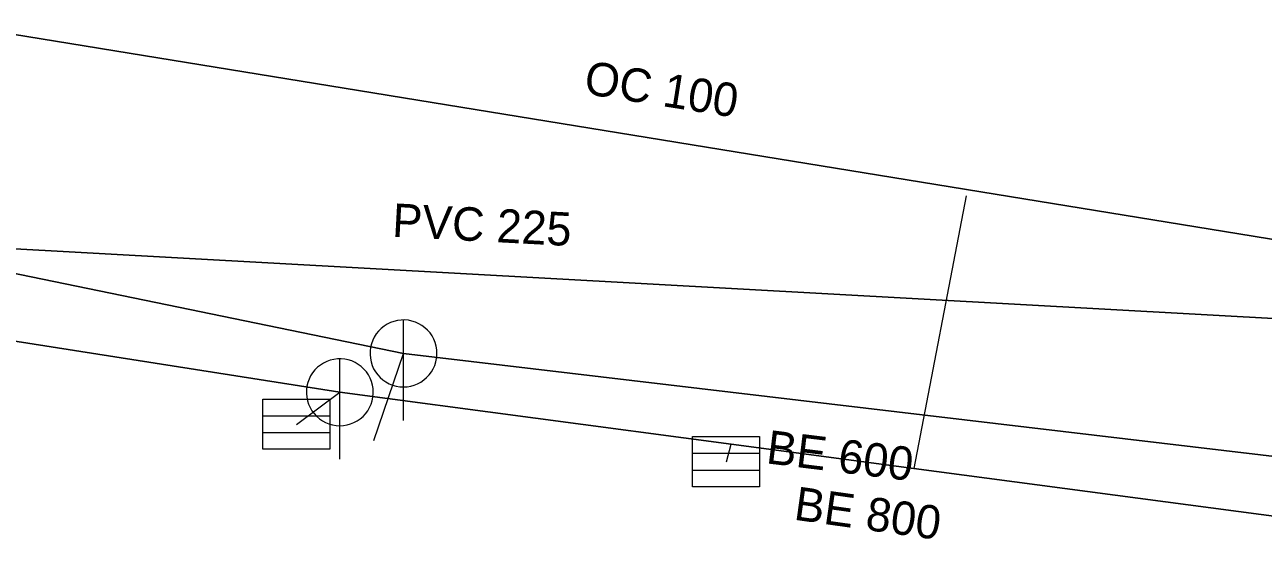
# Model space of a CAD drawing. Extents: x -659250 to -657316, y -997555 to -993684.
# Drawn here: x -658675.14 to -658638.15, y -994986.49 to -994971.06 of the extents above; entities that cross this region are included whole.
import ezdxf

# ---------------------------------------------------------------- set-up
doc = ezdxf.new("R2010")
doc.units = 0
doc.header["$LTSCALE"] = 0.4
doc.layers.add('1', color=7, linetype='Continuous')
for name, color, linetype, lineweight in [('11', 7, 'Continuous', 13), ('14', 7, 'Continuous', 25), ('17', 7, 'Continuous', 25), ('22', 7, 'Continuous', 13)]:
    doc.layers.add(name, color=color, linetype=linetype, lineweight=lineweight)

msp = doc.modelspace()

# ---------------------------------------------------------------- linework, layer by layer
at = {"layer": '11'}
for p, q in [((-658647.02, -994976.17), (-658648.579, -994984.32)), ((-658664.71, -994983.48), (-658663.829, -994980.879)), ((-658667.02, -994983), (-658665.73, -994982.039)), ((-658654.18, -994984.12), (-658654.039, -994983.59))]:
    msp.add_line(p, q, dxfattribs=at)
at = {"layer": '14'}
for p, q in [((-658694.239, -994974.64), (-658663.829, -994980.879)), ((-658663.829, -994980.879), (-658635.789, -994984.199))]:
    msp.add_line(p, q, dxfattribs=at)
for points in [[(-658694.039, -994977.57), (-658683.109, -994979.3), (-658676.77, -994980.3), (-658665.73, -994982.039)], [(-658665.73, -994982.039), (-658654.039, -994983.59), (-658648.579, -994984.32), (-658632.19, -994986.489)]]:
    msp.add_lwpolyline(points, dxfattribs=at)
at = {"layer": '17'}
msp.add_line((-658685.292, -994977.215), (-658636.188, -994979.923), dxfattribs=at)
msp.add_lwpolyline([(-658706.866, -994979.912), (-658705.346, -994979.642), (-658677.234, -994971.061), (-658634.103, -994978.081), (-658613.691, -994984.042), (-658612.274, -994984.09)], dxfattribs=at)
at = {"layer": '22'}
for p, q in [((-658663.829, -994982.879), (-658663.828, -994979.879)), ((-658665.73, -994984.039), (-658665.729, -994981.039)), ((-658668.031, -994982.743), (-658666.031, -994982.743)), ((-658668.031, -994983.243), (-658666.031, -994983.243)), ((-658655.191, -994983.863), (-658653.191, -994983.863)), ((-658655.191, -994984.363), (-658653.191, -994984.363))]:
    msp.add_line(p, q, dxfattribs=at)
for points in [[(-658662.829, -994980.879), (-658662.834, -994980.77), (-658662.852, -994980.662), (-658662.882, -994980.556), (-658662.922, -994980.455), (-658662.974, -994980.358), (-658663.036, -994980.268), (-658663.108, -994980.185), (-658663.188, -994980.111), (-658663.276, -994980.045), (-658663.37, -994979.99), (-658663.47, -994979.945), (-658663.575, -994979.912), (-658663.682, -994979.89), (-658663.791, -994979.88), (-658663.901, -994979.882), (-658664.009, -994979.896), (-658664.116, -994979.921), (-658664.219, -994979.958), (-658664.317, -994980.007), (-658664.409, -994980.065), (-658664.495, -994980.134), (-658664.572, -994980.211), (-658664.641, -994980.297), (-658664.7, -994980.389), (-658664.748, -994980.487), (-658664.785, -994980.59), (-658664.811, -994980.697), (-658664.825, -994980.805), (-658664.828, -994980.915), (-658664.818, -994981.024), (-658664.797, -994981.131), (-658664.763, -994981.235), (-658664.719, -994981.335), (-658664.664, -994981.43), (-658664.598, -994981.518), (-658664.524, -994981.598), (-658664.441, -994981.67), (-658664.351, -994981.732), (-658664.255, -994981.784), (-658664.153, -994981.825), (-658664.048, -994981.855), (-658663.94, -994981.873), (-658663.83, -994981.879), (-658663.721, -994981.873), (-658663.613, -994981.855), (-658663.508, -994981.826), (-658663.406, -994981.785), (-658663.309, -994981.733), (-658663.219, -994981.671), (-658663.136, -994981.6), (-658663.061, -994981.52), (-658662.996, -994981.432), (-658662.94, -994981.338), (-658662.896, -994981.238), (-658662.862, -994981.134), (-658662.84, -994981.026), (-658662.83, -994980.917)], [(-658664.73, -994982.039), (-658664.735, -994981.93), (-658664.753, -994981.822), (-658664.783, -994981.716), (-658664.823, -994981.615), (-658664.875, -994981.518), (-658664.937, -994981.428), (-658665.009, -994981.345), (-658665.089, -994981.271), (-658665.177, -994981.205), (-658665.271, -994981.15), (-658665.371, -994981.105), (-658665.476, -994981.072), (-658665.583, -994981.05), (-658665.692, -994981.04), (-658665.802, -994981.042), (-658665.91, -994981.056), (-658666.017, -994981.081), (-658666.12, -994981.118), (-658666.218, -994981.167), (-658666.31, -994981.225), (-658666.396, -994981.294), (-658666.473, -994981.371), (-658666.542, -994981.457), (-658666.601, -994981.549), (-658666.649, -994981.647), (-658666.686, -994981.75), (-658666.712, -994981.857), (-658666.726, -994981.965), (-658666.729, -994982.075), (-658666.719, -994982.184), (-658666.698, -994982.291), (-658666.664, -994982.395), (-658666.62, -994982.495), (-658666.565, -994982.59), (-658666.499, -994982.678), (-658666.425, -994982.758), (-658666.342, -994982.83), (-658666.252, -994982.892), (-658666.156, -994982.944), (-658666.054, -994982.985), (-658665.949, -994983.015), (-658665.841, -994983.033), (-658665.731, -994983.039), (-658665.622, -994983.033), (-658665.514, -994983.015), (-658665.409, -994982.986), (-658665.307, -994982.945), (-658665.21, -994982.893), (-658665.12, -994982.831), (-658665.037, -994982.76), (-658664.962, -994982.68), (-658664.897, -994982.592), (-658664.841, -994982.498), (-658664.797, -994982.398), (-658664.763, -994982.294), (-658664.741, -994982.186), (-658664.731, -994982.077)], [(-658668.031, -994982.243), (-658666.031, -994982.243), (-658666.031, -994983.743), (-658668.031, -994983.743)], [(-658655.191, -994983.363), (-658653.191, -994983.363), (-658653.191, -994984.863), (-658655.191, -994984.863)]]:
    msp.add_lwpolyline(points, close=True, dxfattribs=at)

# ---------------------------------------------------------------- texts
at = {"layer": '1'}
for s, rotation, p in [('OC 100', 351, (-658658.47, -994973.116)), ('PVC 225 ', 357, (-658664.18, -994977.392)), ('BE 600', 353, (-658653.021, -994984.158)), ('BE 800', 352, (-658652.194, -994985.842))]:
    msp.add_text(s, height=1, rotation=rotation, dxfattribs=at).set_placement(p)

doc.saveas('drawing.dxf')
